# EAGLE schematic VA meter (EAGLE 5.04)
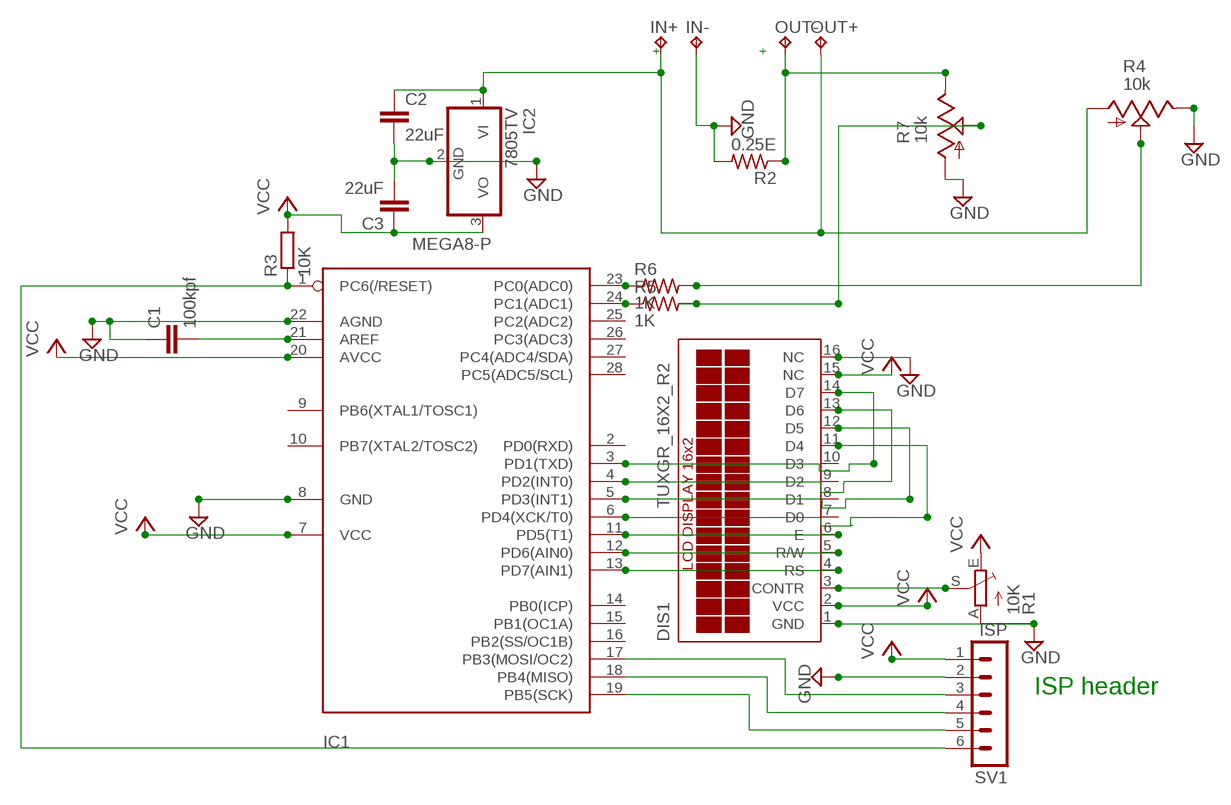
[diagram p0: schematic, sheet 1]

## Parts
C1  100kpf  C5/2.5  [C5B2.5]
C2  22uF  C5/2.5  [C5B2.5]
C3  22uF  C5/2.5  [C5B2.5]
DIS1  TUXGR_16X2_R2  [TUXGR_16X2_R2]
IC1  MEGA8-P  [DIL28-3]
IC2  7805TV  [TO220V]
IN+  TPPAD1-20Y  [P1-20Y]
IN-  TPPAD1-20Y  [P1-20Y]
OUT+  TPPAD1-20Y  [P1-20Y]
OUT-  TPPAD1-20Y  [P1-20Y]
R1  10K  TRIM_EU-CA9V  [CA9V]
R2  0.25E  R-US_0617/17  [0617/17]
R3  10K  R-EU_0207/10  [0207/10]
R4  10k  TRIM_US-RJ9W  [RJ9W]
R5  1K  R-US_0207/10  [0207/10]
R6  1K  R-US_0207/10  [0207/10]
R7  10k  TRIM_US-RJ9W  [RJ9W]
SV1  ISP  MA06-1  [MA06-1]

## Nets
$222: OUT-.1(TP) R2.1 R7.E
+VE: C2.1 IC2.1(VI) IN+.1(TP) OUT+.1(TP) R4.A
AMP_SENSE: R5.2 R7.S
GND: C1.1 C2.2 C3.2 DIS1.1(GND) DIS1.16(NC) IC1.8(GND) IC1.22(AGND) IC2.2(GND) IN-.1(TP) R1.A R2.2 R4.E R7.A SV1.2
MISO: IC1.18(PB4(MISO)) SV1.4
MOSI: IC1.17(PB3(MOSI/OC2)) SV1.3
N$1: DIS1.3(CONTR) R1.S
N$2: DIS1.4(RS) IC1.13(PD7(AIN1))
N$3: DIS1.5(R/W) IC1.12(PD6(AIN0))
N$4: DIS1.6(E) IC1.11(PD5(T1))
N$6: DIS1.12(D5) IC1.5(PD3(INT1))
N$7: DIS1.13(D6) IC1.4(PD2(INT0))
N$8: DIS1.14(D7) IC1.3(PD1(TXD))
N$9: C1.2 IC1.21(AREF)
N$10: DIS1.11(D4) IC1.6(PD4(XCK/T0))
N$13: IC1.24(PC1(ADC1)) R5.1
N$14: IC1.23(PC0(ADC0)) R6.1
RST: IC1.1(PC6(/RESET)) R3.1 SV1.6
SCK: IC1.19(PB5(SCK)) SV1.5
VCC: C3.1 DIS1.2(VCC) DIS1.15(NC) IC1.7(VCC) IC1.20(AVCC) IC2.3(VO) R1.E R3.2 SV1.1
VOLT_SENSE: R4.S R6.2
Unconnected: DIS1.7(D0) DIS1.8(D1) DIS1.9(D2) DIS1.10(D3) IC1.2(PD0(RXD)) IC1.9(PB6(XTAL1/TOSC1)) IC1.10(PB7(XTAL2/TOSC2)) IC1.14(PB0(ICP)) IC1.15(PB1(OC1A)) IC1.16(PB2(SS/OC1B)) IC1.25(PC2(ADC2)) IC1.26(PC3(ADC3)) IC1.27(PC4(ADC4/SDA)) IC1.28(PC5(ADC5/SCL))

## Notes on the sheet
- + | +
- ISP header

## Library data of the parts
C1-C3 = capacitor-wima:C: CAPACITOR
DIS1 = display-lcd:TUXGR_16X2_R2: Tuxgraphics LCD display 16x2 characters reflective, without background light Source: tuxgr_12x2_r2.pdf
IC1 = atmel:MEGA8-P: MICROCONTROLLER 8 Kbytes FLASH, 1 kbytes SRAM, 512 bytes EEPROM, USART, 4-channel 10 bit ADC, 2-channel 8 bit ADC Pin compatible with Atmega48, ATMega88, ATMega168 Source: avr.lbr
IC2 = linear:78*: Positive VOLTAGE REGULATOR Source: http://cache.national.com/ds/LM/LM78L05.pdf http://www.fairchildsemi.com/ds/LM/LM7805.pdf
IN+ IN- OUT+ OUT- = testpad:TP: Test pad
R1 = pot:TRIM_EU-: POTENTIOMETER
R2 R5 R6 = rcl:R-US_: RESISTOR, American symbol
R3 = rcl:R-EU_: RESISTOR, European symbol
R4 R7 = pot:TRIM_US-: POTENTIOMETER
SV1 = con-lstb:MA06-1: PIN HEADER; OC_FARNELL: unknown; OC_NEWARK: unknown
